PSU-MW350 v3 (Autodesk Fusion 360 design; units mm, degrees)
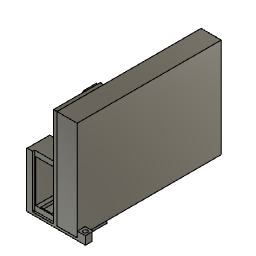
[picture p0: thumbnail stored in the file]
sketch "Sketch1" plane through (0, 0, 0) normal (0, 1, 0) x axis (1, 0, 0)
  line L1 (-34.05, -7.3872) -> (-6.55, -7.3872)
  line L2 (-34.05, -69.3872) -> (-34.05, -7.3872)
  line L3 (-6.55, -69.3872) -> (-34.05, -69.3872)
  line L4 (-6.55, -7.3872) -> (-6.55, -69.3872)
  line L5 (29.5, 0) -> (0, 0)
  line L6 (29.5, -144.8) -> (29.5, 0)
  line L7 (0, -144.8) -> (29.5, -144.8)
  line L8 (0, 0) -> (0, -144.8)
  line L9 (-35.5, -0.1) -> (-5.1, -0.1)
  line L10 (-35.5, -76.6744) -> (-35.5, -0.1)
  line L11 (-5.1, -76.6744) -> (-35.5, -76.6744)
  line L12 (-5.1, -0.1) -> (-5.1, -76.6744)
  line L13 (-5.1, -0.1) -> (-35.5, -76.6744)
  line L14 (-6.55, -69.3872) -> (-34.05, -7.3872)
  line L15 (-44.5, 0) -> (0, 0)
  line L16 (-44.5, -76.7744) -> (-44.5, 0)
  line L17 (-5, -76.7744) -> (-44.5, -76.7744)
  line L18 (-5, -144.8) -> (-5, -76.7744)
  line L19 (0, -144.8) -> (-5, -144.8)
  line L20 (-35.6, 0) -> (-35.6, -76.7744)
  line L21 (-28.3, -2.9315) -> (-28.3, -7.3872)
  line L22 (-12.3, -2.9315) -> (-28.3, -2.9315)
  line L23 (-12.3, -7.3872) -> (-12.3, -2.9315)
  line L24 (-28.3, -73.8428) -> (-28.3, -69.3872)
  line L25 (-12.3, -73.8428) -> (-28.3, -73.8428)
  line L26 (-12.3, -69.3872) -> (-12.3, -73.8428)
  line L27 (-5, 0) -> (-5, -76.7744)
  line L28 (41.5, -8.53) -> (29.5, -8.53)
  line L29 (41.5, 3.47) -> (41.5, -8.53)
  line L30 (-44.5, 3.47) -> (41.5, 3.47)
  line L31 (-44.5, 0) -> (-44.5, 3.47)
  point P1 (0, 0)
  point P14 (-20.3, -38.3872)
  point P15 (-20.3, -38.3872)
  point P16 (0, 0)
  point P21 (0, -144.8)
  point P9 (0, -144.8)
  point P22 (-35.6, -76.7744)
  point P23 (-35.6, 0)
  point P24 (-28.3, -7.3872)
  point P27 (-12.3, -7.3872)
  point P28 (-28.3, -69.3872)
  point P31 (-12.3, -69.3872)
  point P32 (-5, 0)
  point P33 (29.5, -8.53)
  point P17 (-44.5, 0)
  point P37 (-44.5, 0)
  point P6 (0, 0)
  point P7 (29.5, 0)
  point P8 (29.5, -144.8)
  point P4 (-34.05, -69.3872)
  point P5 (-6.55, -69.3872)
  point P3 (-34.05, -7.3872)
  point P11 (-35.5, -0.1)
  point P12 (-35.5, -76.6744)
  point P13 (-5.1, -76.6744)
  point P25 (-28.3, -2.9315)
  point P19 (-5, -76.7744)
  point P34 (41.5, -8.53)
  point P35 (41.5, 3.47)
  horizontal L1
  vertical L2
  horizontal L3
  vertical L4
  horizontal L5
  vertical L6
  horizontal L7
  vertical L8
  coincident P1 L8
  coincident P1 L5
  horizontal L9
  vertical L10
  horizontal L11
  vertical L12
  midpoint L13 P14
  midpoint L14 P15
  coincident P14 P15
  coincident P1 P16
  perpendicular L8 L15
  perpendicular L15 L16
  perpendicular L16 L17
  perpendicular L17 L18
  coincident L8 P21
  perpendicular L8 L19
  coincident P9 P21
  coincident L17 P22
  perpendicular L17 L20
  coincident L15 P23
  coincident L1 P24
  perpendicular L1 L21
  perpendicular L21 L22
  coincident L1 P27
  perpendicular L1 L23
  coincident L3 P28
  perpendicular L3 L24
  perpendicular L24 L25
  coincident L3 P31
  perpendicular L3 L26
  coincident P24 L24
  coincident P27 L26
  equal L21 L24
  perpendicular L15 L27
  coincident L15 P32
  coincident L6 P33
  perpendicular L6 L28
  perpendicular L5 L29
  perpendicular L16 L30
  perpendicular L30 L31
  coincident P17 P37
  dimension "d1" distance P6 P7 = 29.5
  dimension "d2" distance P7 P8 = 144.8
  dimension "d3" distance P4 P5 = 27.5
  dimension "d4" distance P3 P4 = 62
  dimension "d6" distance P11 P12 = 76.5744
  dimension "d7" distance P12 P13 = 30.4
  dimension "d9" distance P1 L9 = 0.1
  dimension "d10" distance P9 L18 = 5
  dimension "d11" distance L11 L17 = 0.1
  dimension "d12" distance L10 L16 = 9
  dimension "d13" distance L10 L20 = 0.1
  dimension "d15" distance P24 P25 = 4.4557
  dimension "d16" distance P14 L24 = 8
  dimension "d17" distance P15 L26 = 8 (= "d16")
  dimension "d18" distance L12 P19 = 0.1
  dimension "d42" distance P33 P34 = 12
  dimension "d43" distance L5 L30 = 3.47
  dimension "d44" distance P34 P35 = 12
extrude "Extrude1" new body sketch "Sketch1" profile of L5 L6 L8 L15 L18 L19 L27 L28 L29 L30 L31 along normal blind 45
extrude "Extrude2" add sketch "Sketch1" profile of L1 L2 L3 L4 L15 L16 L17 L20 L21 L22 L23 L24 L25 L26 L27 along normal blind 33
extrude "Extrude3" cut sketch "Sketch1" profile of L1 L2 L3 L4 L15 L17 L20 L21 L22 L23 L24 L25 L26 L27 along normal blind 3
extrude "Extrude4" sketch "Sketch1" profile of L1 L3 L21 L22 L23 L24 L25 L26 blind 1.5
fillet "Fillet1" radius 1
fillet "Fillet2" radius 3
fillet "Fillet3" radius 1
fillet "Fillet4" radius 1
extrude "Extrude5" new body sketch "Sketch1" profile of L5 L6 L7 L8 along normal blind 210.25 (= "150 mm + 60.25 mm") bodies "PSU"
sketch "Sketch2" plane through (0, 0, 0) normal (-1, 0, 0) x axis (0, -1, 0)
  line L1 (0, 144.8) -> (0, 0)
  line L2 (-210.25, 144.8) -> (0, 144.8)
  line L3 (-210.25, 0) -> (-210.25, 144.8)
  line L4 (0, 0) -> (-210.25, 0)
  line L5 (-180.125, 47.4) -> (-30.125, 47.4)
  line L6 (-180.125, 97.4) -> (-180.125, 47.4)
  line L7 (-30.125, 97.4) -> (-180.125, 97.4)
  line L8 (-30.125, 47.4) -> (-30.125, 97.4)
  line L9 (0, 144.8) -> (-210.25, 0)
  line L10 (-30.125, 47.4) -> (-180.125, 97.4)
  circle C1 centre (-180.125, 97.4) radius 2.25
  circle C2 centre (-180.125, 47.4) radius 2.25
  circle C3 centre (-30.125, 47.4) radius 2.25
  circle C4 centre (-30.125, 97.4) radius 2.25
  point P5 (-210.25, 0)
  point P10 (-210.25, 0)
  point P3 (0, 144.8)
  point P11 (0, 144.8)
  point P12 (-105.125, 72.4)
  point P13 (-105.125, 72.4)
  point P8 (-180.125, 97.4)
  point P14 (-180.125, 97.4)
  point P7 (-180.125, 47.4)
  point P15 (-180.125, 47.4)
  point P6 (-30.125, 47.4)
  point P16 (-30.125, 47.4)
  point P9 (-30.125, 97.4)
  point P17 (-30.125, 97.4)
  horizontal L5
  vertical L6
  horizontal L7
  vertical L8
  coincident P5 P10
  coincident P3 P11
  midpoint L9 P12
  midpoint L10 P13
  coincident P12 P13
  coincident P8 P14
  coincident P7 P15
  coincident P6 P16
  coincident P9 P17
  equal C3 C4
  equal C2 C4
  equal C1 C2
  dimension "d34" distance P6 P9 = 50
  dimension "d35" distance P8 P9 = 150
  dimension "d36" diameter C4 = 4.5
extrude "Extrude6" cut sketch "Sketch2" + "Sketch3" profile of S1:C4 blind 50
sketch "Sketch3" plane through (0, 0, 0) normal (0, 0, -1) x axis (1, 0, 0)
  line L1 (0, 0) -> (29.5, 0)
  line L2 (0, -210.25) -> (0, 0)
  line L3 (29.5, -210.25) -> (0, -210.25)
  line L4 (29.5, 0) -> (29.5, -210.25)
  line L5 (12.5, -30.125) -> (12.5, -180.125)
  circle C1 centre (12.5, -30.125) radius 2.125
  circle C2 centre (12.5, -180.125) radius 2.125
  point P7 (12.5, -180.125)
  point P8 (12.5, -180.125)
  point P6 (12.5, -30.125)
  point P9 (12.5, -30.125)
  point P10 (0, -30.125)
  point P11 (0, -180.125)
  coincident P7 P8
  vertical L5
  coincident P6 P9
  horizontal P6 P10
  horizontal P7 P11
  equal C1 C2
  dimension "d40" diameter C1 = 4.25
  dimension "d41" distance L2 L5 = 12.5
extrude "Extrude7" cut sketch "Sketch3" profile of C1 along normal blind 25
fillet "Fillet5" radius 1
sketch "Sketch4" plane through (0, 0, -3.47) normal (0, 0, -1) x axis (1, 0, 0)
  line L1 (-44.5, 0) -> (41.5, 0)
  line L2 (-44.5, -45) -> (-44.5, 0)
  line L3 (41.5, -45) -> (-44.5, -45)
  line L4 (41.5, 0) -> (41.5, -45)
  line L5 (41.5, -11.54) -> (29.5, -11.54)
  line L6 (-5, -33) -> (-5, -45)
  line L7 (-44.5, -33) -> (-5, -33)
  line L8 (29.5, -210.25) -> (29.5, 0)
  line L9 (-0.1, -186.125) -> (-0.1, -174.125)
  line L10 (18.5, -186.125) -> (-0.1, -186.125)
  line L11 (18.5, -174.125) -> (18.5, -186.125)
  line L12 (-0.1, -174.125) -> (18.5, -174.125)
  line L13 (-12.84, -174.125) -> (-0.1, -174.125)
  line L14 (-12.84, -186.125) -> (-12.84, -174.125)
  line L15 (-0.1, -186.125) -> (-12.84, -186.125)
  line L16 (0, -210.25) -> (0, 0)
  line L17 (-6.47, -180.125) -> (-12.84, -180.125)
  line L18 (-2.64, -186.125) -> (-2.64, -174.125)
  circle C1 centre (12.5, -30.125) radius 2.125
  circle C2 centre (-38.96, -5.54) radius 7.5
  circle C3 centre (-38.96, -5.54) radius 3
  circle C4 centre (35.96, -5.54) radius 3
  circle C5 centre (35.96, -5.54) radius 7.5
  circle C6 centre (-6.47, -180.125) radius 3
  circle C7 centre (-6.47, -180.125) radius 7.5
  circle C8 centre (12.5, -180.125) radius 2.125
  point P9 (-41.96, -5.54)
  point P7 (-38.96, -5.54)
  point P10 (-38.96, -2.54)
  point P8 (-38.96, -5.54)
  point P11 (35.96, -5.54)
  point P15 (38.96, -5.54)
  point P12 (35.96, -5.54)
  point P17 (41.5, -11.54)
  point P18 (-5, -45)
  point P16 (29.5, -11.54)
  point P20 (-44.5, -33)
  point P21 (-44.5, -33)
  point P24 (-5, -45)
  point P25 (12.5, -180.125)
  point P26 (12.5, -180.125)
  point P13 (-6.47, -180.125)
  point P27 (-0.1, -174.125)
  point P31 (-0.1, -174.125)
  point P28 (-0.1, -186.125)
  point P34 (-0.1, -186.125)
  point P37 (-12.84, -180.125)
  point P14 (-6.47, -180.125)
  point P38 (-6.47, -180.125)
  point P39 (-3.47, -180.125)
  point P40 (-9.47, -180.125)
  point P41 (-2.64, -174.125)
  point P42 (-2.64, -186.125)
  point P32 (-12.84, -174.125)
  point P33 (-12.84, -186.125)
  concentric C2 C3
  coincident C3 P9
  horizontal P7 P9
  coincident C3 P10
  vertical P8 P10
  concentric C4 C5
  equal C2 C5
  equal C3 C4
  horizontal P7 P11
  concentric C6 C7
  equal C3 C6
  equal C2 C7
  coincident C4 P15
  horizontal P12 P15
  coincident L4 P17
  perpendicular L4 L5
  coincident L3 P18
  perpendicular L3 L6
  perpendicular L6 L7
  coincident P16 L8
  coincident P20 P21
  coincident P18 P24
  coincident P25 P26
  horizontal P13 P26
  vertical L9
  perpendicular L9 L10
  perpendicular L10 L11
  perpendicular L9 L12
  coincident P27 P31
  perpendicular L9 L13
  perpendicular L12 L14
  perpendicular L9 L15
  coincident P28 P34
  midpoint L14 P37
  perpendicular L14 L17
  coincident P14 P38
  coincident C6 P39
  coincident C6 P40
  coincident L17 P40
  horizontal P13 P39
  coincident L13 P41
  coincident L15 P42
  perpendicular L15 L18
  dimension "d48" diameter C3 = 6
  dimension "d49" diameter C2 = 15
  dimension "d50" = 6
  dimension "d52" distance L2 P9 = 2.54
  dimension "d53" distance L1 P10 = 2.54 (= "d52")
  dimension "d55" distance L4 P15 = 2.54
  dimension "d56" distance P11 L5 = 6
  dimension "d60" diameter C8 = 4.25
  dimension "d61" distance L9 L16 = 0.1
  dimension "d62" distance P26 L11 = 6
  dimension "d63" distance P32 P33 = 12
  dimension "d64" distance P27 P39 = 3.37
  dimension "d65" distance L14 P40 = 3.37 (= "d64")
  dimension "d66" distance P31 L18 = 2.54
extrude "Extrude9" new body sketch "Sketch4" profile of C6 C7 C8 L9 L10 L11 L12 L13 L14 L15 L16 L18 to an object bodies "Step"
extrude "Extrude8" cut sketch "Sketch4" profile of L2 L3 L4 C3 C4 C5 L5 L6 L7 L8 against normal blind 12
extrude "Extrude10" add sketch "Sketch4" profile of C6 C7 L9 L13 L14 L15 L18 against normal blind 12
extrude "Extrude11" add sketch "Sketch4" profile of C7 L9 L13 L15 L18 against normal blind 60
extrude "Extrude12" cut sketch "Sketch2" profile of C2 along normal blind 25
sketch "Sketch5" plane through (-5, 0, 0) normal (-1, 0, 0) x axis (0, -1, 0)
  line L1 (-33, 79.7744) -> (-33, -3.47)
  line L2 (-3, 79.7744) -> (-33, 79.7744)
  line L3 (-3, 1) -> (-3, 79.7744)
  line L4 (0, 1) -> (-3, 1)
  line L5 (0, 144.8) -> (0, 1)
  line L6 (-45, 144.8) -> (0, 144.8)
  line L7 (-45, -3.47) -> (-45, 144.8)
  line L8 (-33, -3.47) -> (-45, -3.47)
  line L9 (-47, 97.8) -> (-67, 97.8)
  line L10 (-47, 72.8) -> (-47, 97.8)
  line L11 (-67, 72.8) -> (-47, 72.8)
  line L12 (-67, 97.8) -> (-67, 72.8)
  line L13 (-67, 117.8) -> (-67, 97.8)
  line L14 (-47, 117.8) -> (-67, 117.8)
  line L15 (-47, 97.8) -> (-47, 117.8)
  line L16 (-67, 137.8) -> (-67, 117.8)
  line L17 (-47, 137.8) -> (-67, 137.8)
  line L18 (-47, 117.8) -> (-47, 137.8)
  line L19 (-67, 47.8) -> (-67, 72.8)
  line L20 (-47, 47.8) -> (-67, 47.8)
  line L21 (-47, 72.8) -> (-47, 47.8)
  line L22 (-67, 32.8) -> (-67, 47.8)
  line L23 (-47, 32.8) -> (-67, 32.8)
  line L24 (-47, 47.8) -> (-47, 32.8)
  line L25 (-47, 57.8) -> (-67, 57.8)
  line L26 (-70, 144.8) -> (-45, 144.8)
  line L27 (-70, -3.47) -> (-70, 144.8)
  line L28 (-45, -3.47) -> (-70, -3.47)
  line L29 (-46, 142.8) -> (-68, 142.8)
  line L30 (-46, 27.8) -> (-46, 142.8)
  line L31
  line L32 (-68, 142.8) -> (-68, 27.8)
  circle C1 centre (-30.125, 97.4) radius 2.25
  circle C2 centre (-57, 137.8) radius 2.7
  circle C3 centre (-57, 117.8) radius 2.7
  circle C4 centre (-57, 97.8) radius 2.7
  circle C5 centre (-57, 72.8) radius 2.7
  circle C6 centre (-57, 47.8) radius 2.7
  circle C7 centre (-57, 32.8) radius 2.7
  circle C8 centre (-63.5, 137.8) radius 2.7
  circle C9 centre (-63.5, 117.8) radius 2.7
  circle C10 centre (-63.5, 97.8) radius 2.7
  circle C11 centre (-63.5, 72.8) radius 2.7
  circle C12 centre (-63.5, 47.8) radius 2.7
  circle C13 centre (-63.5, 32.8) radius 2.7
  circle C14 centre (-50.5, 32.8) radius 2.7
  circle C15 centre (-50.5, 117.8) radius 2.7
  circle C16 centre (-50.5, 47.8) radius 2.7
  circle C17 centre (-50.5, 72.8) radius 2.7
  circle C18 centre (-50.5, 97.8) radius 2.7
  circle C19 centre (-50.5, 137.8) radius 2.7
  point P12 (-47, 97.8)
  point P17 (-47, 97.8)
  point P16 (-47, 117.8)
  point P20 (-47, 117.8)
  point P13 (-47, 72.8)
  point P23 (-47, 72.8)
  point P22 (-47, 47.8)
  point P26 (-47, 47.8)
  point P27 (-67, 57.8)
  point P28 (-47, 57.8)
  point P29 (-57, 137.8)
  point P30 (-57, 117.8)
  point P31 (-57, 97.8)
  point P32 (-57, 72.8)
  point P33 (-57, 47.8)
  point P34 (-57, 32.8)
  point P38 (-63.5, 72.8)
  point P39 (-63.5, 47.8)
  point P36 (-63.5, 117.8)
  point P37 (-63.5, 97.8)
  point P40 (-63.5, 32.8)
  point P35 (-63.5, 137.8)
  point P45 (-50.5, 72.8)
  point P46 (-50.5, 47.8)
  point P42 (-50.5, 117.8)
  point P44 (-50.5, 97.8)
  point P43 (-50.5, 32.8)
  point P41 (-50.5, 137.8)
  point P9 (-45, 144.8)
  point P47 (-45, 144.8)
  point P50 (-45, -3.47)
  point P51 (-45, -3.47)
  point P14 (-67, 72.8)
  point P19 (-47, 137.8)
  point P25 (-47, 32.8)
  point P18 (-67, 137.8)
  horizontal L9
  vertical L10
  horizontal L11
  vertical L12
  perpendicular L9 L13
  perpendicular L13 L14
  perpendicular L14 L15
  coincident P12 P17
  perpendicular L14 L16
  perpendicular L16 L17
  perpendicular L17 L18
  coincident P16 P20
  perpendicular L11 L19
  perpendicular L19 L20
  perpendicular L20 L21
  coincident P13 P23
  perpendicular L20 L22
  perpendicular L22 L23
  perpendicular L20 L24
  coincident P22 P26
  coincident L19 P27
  coincident L21 P28
  perpendicular L21 L25
  midpoint L17 P29
  midpoint L14 P30
  midpoint L9 P31
  midpoint L11 P32
  midpoint L20 P33
  midpoint L23 P34
  equal C5 C7
  equal C5 C6
  equal C2 C6
  equal C2 C3
  equal C3 C4
  vertical P38 P39
  vertical P36 P38
  vertical P36 P37
  vertical P37 P40
  vertical P35 P40
  equal C10 C12
  equal C8 C12
  equal C8 C11
  equal C11 C13
  equal C9 C13
  equal C2 C8
  vertical P45 P46
  vertical P42 P45
  vertical P42 P44
  vertical P43 P44
  vertical P41 P43
  equal C16 C18
  equal C16 C19
  equal C17 C19
  equal C14 C17
  equal C14 C15
  horizontal P35 P41
  horizontal P36 P42
  horizontal P37 P44
  horizontal P38 P45
  horizontal P39 P46
  horizontal P40 P43
  coincident L17 P35
  equal C2 C19
  coincident L14 P36
  coincident L9 P37
  coincident L11 P38
  coincident L20 P39
  coincident L23 P40
  coincident P9 P47
  perpendicular L7 L26
  perpendicular L6 L27
  coincident L7 P50
  perpendicular L7 L28
  coincident L28 P51
  horizontal L29
  vertical L30
  horizontal L31
  vertical L32
  dimension "d75" distance P13 P14 = 20
  dimension "d76" distance P12 P13 = 25
  dimension "d77" distance P16 P17 = 20
  dimension "d78" distance P19 P20 = 20
  dimension "d79" distance P22 P23 = 25
  dimension "d80" distance P25 P26 = 15
  dimension "d81" distance P13 L25 = 15
  dimension "d82" diameter C2 = 5.4
  dimension "d83" distance P29 P35 = 6.5
  dimension "d84" distance P29 P41 = 6.5
  dimension "d85" distance L7 P19 = 2
  dimension "d86" distance P19 L26 = 7
  dimension "d87" distance P18 L27 = 3
  dimension "d101" distance P43 L31 = 5
  dimension "d102" distance P25 L30 = 1
  dimension "d103" distance L22 L32 = 1
  dimension "d104" distance P41 L29 = 5
extrude "Extrude13" new body sketch "Sketch5" profile of L7 C2 C3 C4 C5 C6 C7 C8 C9 C10 C11 C12 C13 C14 C15 C16 C17 C18 C19 L26 L27 L28 to an object
extrude "Extrude14" add sketch "Sketch5" profile of C2 C3 C4 C5 C6 C7 C8 C9 C10 C11 C12 C13 C14 C15 C16 C17 C18 C19 L29 L30 L31 L32 along normal blind 4
extrude "Extrude15" cut sketch "Sketch5" profile of C2 C3 C4 C5 C6 C7 C8 C9 C10 C11 C12 C13 C14 C15 C16 C17 C18 C19 against normal blind 3
combine "Combine1"
chamfer "Chamfer1" distance 4
fillet "Fillet16" radius 2
fillet "Fillet17" radius 1
offset_faces "OffsetFaces1" distance -0.1
offset_faces "OffsetFaces2" distance -0.1
fillet "Fillet7" radius 1
fillet "Fillet8" radius 2
fillet "Fillet9" radius 3
fillet "Fillet10" radius 2
fillet "Fillet11" radius 1
fillet "Fillet12" radius 2
fillet "Fillet13" radius 2
fillet "Fillet14" radius 2
fillet "Fillet15" radius 2
named bodies: "Front", "PSU", "Step"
